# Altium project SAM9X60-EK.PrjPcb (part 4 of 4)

## Sheet 13 - On Board JLINK.SchDoc
size B; CompanyName: Microchip Technology Inc.; Organization: Microchip Technology; Address1: 2355 West Chandler Blvd.; Address2: Chandler, AZ  85224; Address4: USA; DocumentNumber: 13; SheetNumber: 13; SheetTotal: 13; SheetTitle: On Board JLINK
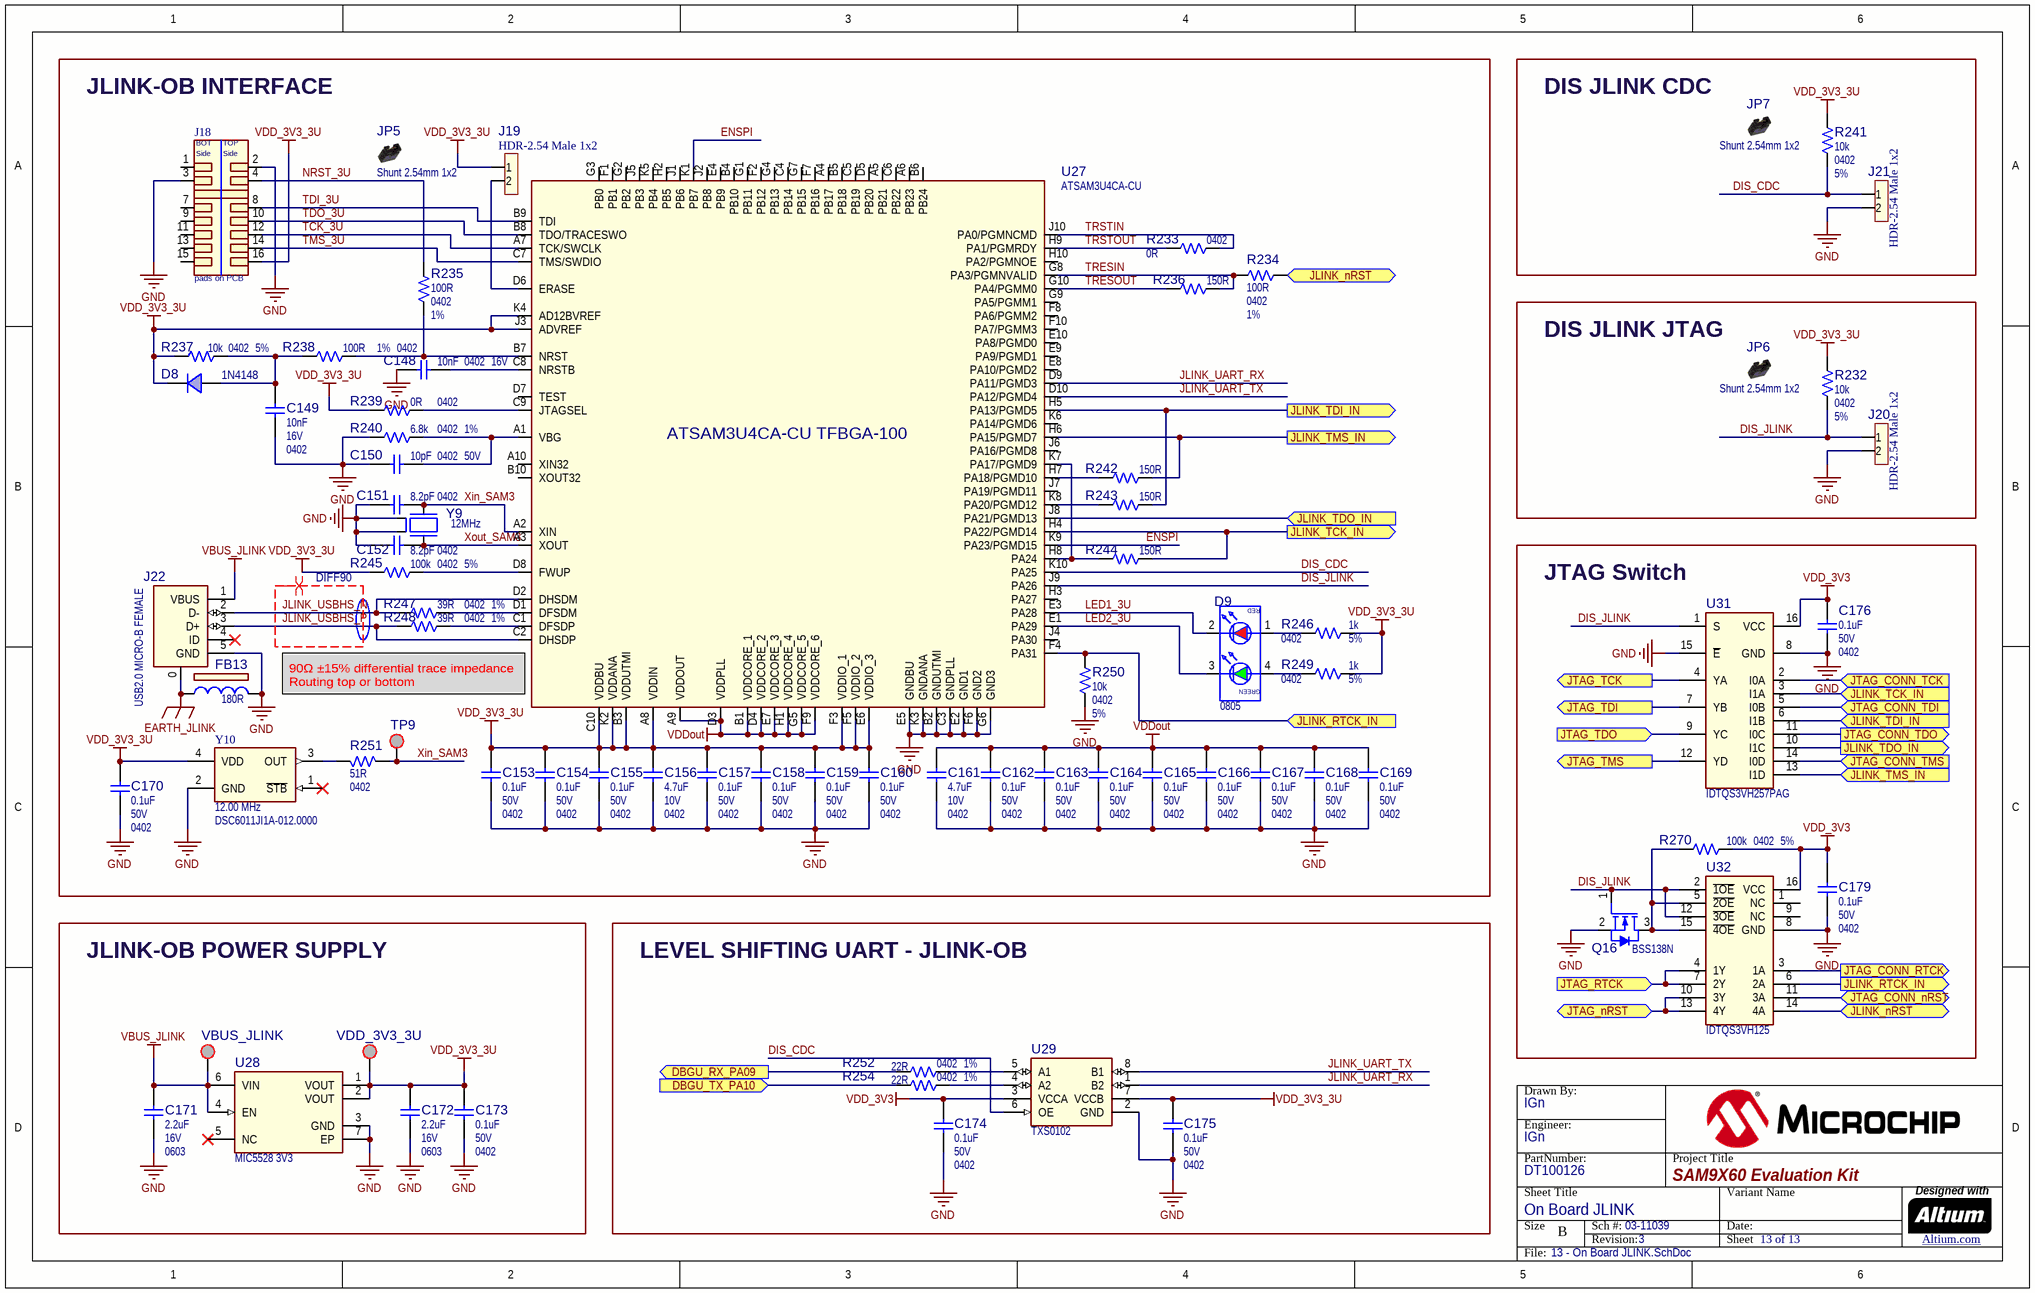
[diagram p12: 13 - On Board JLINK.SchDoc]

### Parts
(Parts that share a designator on the sheet are numbered #1, #2 ... from top to bottom, then left to right.)
?#13  (no value)  (graphical)
C148  value 10nF  Voltage: 16V  Package: 0402  [CAP_C_0402]  (hidden comment: Capacitor NP)
C149  value 10nF  Voltage: 16V  Package: 0402  [CAP_C_0402]  (hidden comment: Capacitor NP)
C150  value 10pF  Voltage: 50V  Package: 0402  [CAP_C_0402]  (hidden comment: Capacitor NP)
C151  value 8.2pF  Package: 0402  [CAP_C_0402]  (hidden comment: Capacitor NP)
C152  value 8.2pF  Package: 0402  [CAP_C_0402]  (hidden comment: Capacitor NP)
C153  value 0.1uF  Voltage: 50V  Package: 0402  [CAP_C_0402]  (hidden comment: Capacitor NP)
C154  value 0.1uF  Voltage: 50V  Package: 0402  [CAP_C_0402]  (hidden comment: Capacitor NP)
C155  value 0.1uF  Voltage: 50V  Package: 0402  [CAP_C_0402]  (hidden comment: Capacitor NP)
C156  value 4.7uF  Voltage: 10V  Package: 0402  [CAP_C_0402]  (hidden comment: Capacitor NP)
C157  value 0.1uF  Voltage: 50V  Package: 0402  [CAP_C_0402]  (hidden comment: Capacitor NP)
C158  value 0.1uF  Voltage: 50V  Package: 0402  [CAP_C_0402]  (hidden comment: Capacitor NP)
C159  value 0.1uF  Voltage: 50V  Package: 0402  [CAP_C_0402]  (hidden comment: Capacitor NP)
C160  value 0.1uF  Voltage: 50V  Package: 0402  [CAP_C_0402]  (hidden comment: Capacitor NP)
C161  value 4.7uF  Voltage: 10V  Package: 0402  [CAP_C_0402]  (hidden comment: Capacitor NP)
C162  value 0.1uF  Voltage: 50V  Package: 0402  [CAP_C_0402]  (hidden comment: Capacitor NP)
C163  value 0.1uF  Voltage: 50V  Package: 0402  [CAP_C_0402]  (hidden comment: Capacitor NP)
C164  value 0.1uF  Voltage: 50V  Package: 0402  [CAP_C_0402]  (hidden comment: Capacitor NP)
C165  value 0.1uF  Voltage: 50V  Package: 0402  [CAP_C_0402]  (hidden comment: Capacitor NP)
C166  value 0.1uF  Voltage: 50V  Package: 0402  [CAP_C_0402]  (hidden comment: Capacitor NP)
C167  value 0.1uF  Voltage: 50V  Package: 0402  [CAP_C_0402]  (hidden comment: Capacitor NP)
C168  value 0.1uF  Voltage: 50V  Package: 0402  [CAP_C_0402]  (hidden comment: Capacitor NP)
C169  value 0.1uF  Voltage: 50V  Package: 0402  [CAP_C_0402]  (hidden comment: Capacitor NP)
C170  value 0.1uF  Voltage: 50V  Package: 0402  [CAP_C_0402]  (hidden comment: Capacitor NP)
C171  value 2.2uF  Voltage: 16V  Package: 0603  [CAP_C_0603]  (hidden comment: Capacitor NP)
C172  value 2.2uF  Voltage: 16V  Package: 0603  [CAP_C_0603]  (hidden comment: Capacitor NP)
C173  value 0.1uF  Voltage: 50V  Package: 0402  [CAP_C_0402]  (hidden comment: Capacitor NP)
C174  value 0.1uF  Voltage: 50V  Package: 0402  [CAP_C_0402]  (hidden comment: Capacitor NP)
C175  value 0.1uF  Voltage: 50V  Package: 0402  [CAP_C_0402]  (hidden comment: Capacitor NP)
C176  value 0.1uF  Voltage: 50V  Package: 0402  [CAP_C_0402]  (hidden comment: Capacitor NP)
C179  value 0.1uF  Voltage: 50V  Package: 0402  [CAP_C_0402]  (hidden comment: Capacitor NP)
D8  value 1N4148  [SOD-323]  (hidden comment: Diode Single)
D9  Package: 0805  [LED_DUAL_SMD_2x1.25mm]  (hidden comment: LED DUAL 4 pin)
FB13  value 180R  [IND_C_0603]  (hidden comment: Ferrite Bead)
J18  pads on PCB  [CON_EDGE-CARD_PCB_RA_MEC1-108-02-F-D-RA1-SL]  (no BOM)
J19  value HDR-2.54 Male 1x2  [HDR_M_2.54_1x2]  (hidden comment: Header 1x2)
J20  value HDR-2.54 Male 1x2  [HDR_M_2.54_1x2]  (hidden comment: Header 1x2)
J21  value HDR-2.54 Male 1x2  [HDR_M_2.54_1x2]  (hidden comment: Header 1x2)
J22  value USB2.0 MICRO-B FEMALE  [CON_USB_Micro-AB_SMD_TH_RA_FCI_10118194-0001LF]  (hidden comment: CON USB2.0 Mini_Micro)
JP5  value Shunt 2.54mm 1x2  [Jumper_Mechanical]  (hidden comment: Jumper Mechanical)  (mechanical)
JP6  value Shunt 2.54mm 1x2  [Jumper_Mechanical]  (hidden comment: Jumper Mechanical)  (mechanical)
JP7  value Shunt 2.54mm 1x2  [Jumper_Mechanical]  (hidden comment: Jumper Mechanical)  (mechanical)
Q16  value BSS138N  [SOT-23-3]  (hidden comment: Transistor MOS-N GSD)
R232  value 10k  Package: 0402  Tolerance: 5%  [RES_C_0402]  (hidden comment: Resistor)
R233  value 0R  Package: 0402  [RES_C_0402]  (hidden comment: Resistor)
R234  value 100R  Package: 0402  Tolerance: 1%  [RES_C_0402]  (hidden comment: Resistor)
R235  value 100R  Package: 0402  Tolerance: 1%  [RES_C_0402]  (hidden comment: Resistor)
R236  value 150R  [RES_C_0402]  (hidden comment: Resistor)
R237  value 10k  Package: 0402  Tolerance: 5%  [RES_C_0402]  (hidden comment: Resistor)
R238  value 100R  Package: 0402  Tolerance: 1%  [RES_C_0402]  (hidden comment: Resistor)
R239  value 0R  Package: 0402  [RES_C_0402]  (hidden comment: Resistor)
R240  value 6.8k  Package: 0402  Tolerance: 1%  [RES_C_0402]  (hidden comment: Resistor)
R241  value 10k  Package: 0402  Tolerance: 5%  [RES_C_0402]  (hidden comment: Resistor)
R242  value 150R  [RES_C_0402]  (hidden comment: Resistor)
R243  value 150R  [RES_C_0402]  (hidden comment: Resistor)
R244  value 150R  [RES_C_0402]  (hidden comment: Resistor)
R245  value 100k  Package: 0402  Tolerance: 5%  [RES_C_0402]  (hidden comment: Resistor)
R246  value 1k  Package: 0402  Tolerance: 5%  [RES_C_0402]  (hidden comment: Resistor)
R247  value 39R  Package: 0402  Tolerance: 1%  [RES_C_0402]  (hidden comment: Resistor)
R248  value 39R  Package: 0402  Tolerance: 1%  [RES_C_0402]  (hidden comment: Resistor)
R249  value 1k  Package: 0402  Tolerance: 5%  [RES_C_0402]  (hidden comment: Resistor)
R250  value 10k  Package: 0402  Tolerance: 5%  [RES_C_0402]  (hidden comment: Resistor)
R251  value 51R  Package: 0402  [RES_C_0402]  (hidden comment: Resistor)
R252  value 22R  Package: 0402  Tolerance: 1%  [RES_C_0402]  (hidden comment: Resistor)
R254  value 22R  Package: 0402  Tolerance: 1%  [RES_C_0402]  (hidden comment: Resistor)
R270  value 100k  Package: 0402  Tolerance: 5%  [RES_C_0402]  (hidden comment: Resistor)
TP9  SMD Test Point  [TP_1x1_SMD]  (value not drawn)  (no BOM)
U27  ATSAM3U4CA-CU TFBGA-100  value ATSAM3U4CA-CU  [TFBGA-100_P0.8_9x9x1.1]
U28  value MIC5528 3V3  [DFN-6_1.2x1.2]  (hidden comment: MIC5528MT DFN-6)
U29  TXS0102  [US-8]
U31  value IDTQS3VH257PAG  [TSSOP-16]  (hidden comment: IDTQS3VH257 TSSOP-16)
U32  value IDTQS3VH125  [QSOP-16]  (hidden comment: IDTQS3VH125 SSOP-16)
VBUS_JLINK  SMD Test Point  [TP_1x1_SMD]  (value not drawn)  (no BOM)
VDD_3V3_3U  SMD Test Point  [TP_1x1_SMD]  (value not drawn)  (no BOM)
Y9  value 12MHz  [CRYSTAL_L7.5W5.2H1.4]  (hidden comment: Crystal 4 Pins)
Y10  value 12.00 MHz  Manufacturer Part Number 1: DSC6011JI1A-012.0000  [OSCILLATOR_DSC60000L2.5W2.0H0.89]  (hidden comment: OSCILLATOR DSC60XX)

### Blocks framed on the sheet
JLINK-OB INTERFACE: C148-C170 D8 D9 FB13 J18 J19 J22 JP5 R233-R240 R242-R251 TP9 U27 Y9 Y10
DIS JLINK CDC: J21 JP7 R241
DIS JLINK JTAG: J20 JP6 R232
JTAG Switch: C176 C179 Q16 R270 U31 U32
JLINK-OB POWER SUPPLY: C171-C173 U28 VBUS_JLINK VDD_3V3_3U
LEVEL SHIFTING UART - JLINK-OB: C174 C175 R252 R254 U29

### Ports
DBGU_RX_PA09 (out), DBGU_TX_PA10 (in), JLINK_nRST (bidir), JLINK_RTCK_IN (in), JLINK_RTCK_IN (out), JLINK_TCK_IN (in), JLINK_TCK_IN (out), JLINK_TDI_IN (in), JLINK_TDI_IN (out), JLINK_TDO_IN (in), JLINK_TDO_IN (out), JLINK_TMS_IN (in), JLINK_TMS_IN (out), JTAG_CONN_nRST (bidir), JTAG_CONN_RTCK (out), JTAG_CONN_TCK (in), JTAG_CONN_TDI (in), JTAG_CONN_TDO (out), JTAG_CONN_TMS (in), JTAG_nRST (bidir), JTAG_RTCK (in), JTAG_TCK (out), JTAG_TDI (out), JTAG_TDO (in), JTAG_TMS (out)

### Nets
EARTH_JLINK: FB13.1 J22.0(SHLD)
GND: C148.1 C149.1 C150.2 C151.2 C152.2 C153.2 C154.1 C155.2 C156.1 C157.1 C158.1 C159.1 C160.1 C161.1 C162.1 C163.2 C164.2 C165.2 C166.2 C167.2 C168.2 C169.1 C170.1 C171.2 C172.1 C173.1 C174.1 C175.1 C176.2 C179.2 FB13.2 J18.2 J18.3 J20.2 J21.2 J22.5(GND) Q16.2(S) R240.1 R250.2 U27.B2(GNDUTMI) U27.C3(GNDPLL) U27.E2(GND1) U27.E5(GNDBU) U27.F6(GND2) U27.G6(GND3) U27.K3(GNDANA) U28.3(GND) U28.7(EP) U29.2(GND) U31.8(GND) U31.15(~{E}) U32.8(GND) Y9.2(GND) Y9.4(GND) Y10.2(GND)
VBUS_JLINK: C171.1 J22.1(VBUS) U28.4(EN) U28.6(VIN) VBUS_JLINK.1
VDD_3V3: C174.2 C176.1 C179.1 R270.1 U29.3(VCCA) U31.16(VCC) U32.16(VCC)
VDD_3V3_3U: C153.1 C154.2 C155.1 C156.2 C157.2 C158.2 C159.2 C160.2 C170.2 C172.2 C173.2 C175.2 D8.2(K) J18.16 J19.1 R232.1 R237.1 R239.1 R241.1 R245.1 R246.1 R249.1 U27.A8(VDDIN) U27.B3(VDDUTMI) U27.C10(VDDBU) U27.E6(VDDIO_3) U27.F3(VDDIO_1) U27.F5(VDDIO_2) U27.J3(ADVREF) U27.K2(VDDANA) U27.K4(AD12BVREF) U28.1(VOUT) U28.2(VOUT) U29.7(VCCB) VDD_3V3_3U.1 Y10.4(VDD)
VDDout: C161.2 C162.2 C163.1 C164.1 C165.1 C166.1 C167.1 C168.1 C169.2 U27.A9(VDDOUT) U27.B1(VDDCORE_1) U27.D3(VDDPLL) U27.D4(VDDCORE_2) U27.E7(VDDCORE_3) U27.F9(VDDCORE_6) U27.G5(VDDCORE_5) U27.H1(VDDCORE_4)
DBGU_RX_PA09: R252.1 ; port DBGU_RX_PA09
DBGU_TX_PA10: R254.1 ; port DBGU_TX_PA10
DIS_CDC: J21.1 R241.2 U27.K10(PA25) U29.6(OE)
DIS_JLINK: J20.1 Q16.1(G) R232.2 U27.J9(PA26) U31.1(S) U32.2(~{1OE}) U32.12(~{3OE})
ENSPI: U27.K1(PB7) U27.K9(PA23/PGMD15)
JLINK_nRST: R234.2 U32.14(4A) ; port JLINK_nRST
JLINK_RTCK_IN: R250.1 U27.F4(PA31) U32.6(2A) ; port JLINK_RTCK_IN
JLINK_TCK_IN: R244.2 U27.H4(PA22/PGMD14) U31.3(I1A) ; port JLINK_TCK_IN
JLINK_TDI_IN: R243.2 U27.H5(PA13/PGMD5) U31.6(I1B) ; port JLINK_TDI_IN
JLINK_TDO_IN: U27.J8(PA21/PGMD13) U31.10(I1C) ; port JLINK_TDO_IN
JLINK_TMS_IN: R242.2 U27.H6(PA15/PGMD7) U31.13(I1D) ; port JLINK_TMS_IN
JLINK_UART_RX: U27.D9(PA11/PGMD3) U29.1(B2)
JLINK_UART_TX: U27.D10(PA12/PGMD4) U29.8(B1)
JLINK_USBHS_N: J22.2(D-) R247.1 U27.D2(DHSDM)
JLINK_USBHS_P: J22.3(D+) R248.1 U27.C2(DHSDP)
JTAG_CONN_nRST: U32.11(3A) ; port JTAG_CONN_nRST
JTAG_CONN_RTCK: U32.3(1A) ; port JTAG_CONN_RTCK
JTAG_CONN_TCK: U31.2(I0A) ; port JTAG_CONN_TCK
JTAG_CONN_TDI: U31.5(I0B) ; port JTAG_CONN_TDI
JTAG_CONN_TDO: U31.11(I0C) ; port JTAG_CONN_TDO
JTAG_CONN_TMS: U31.14(I0D) ; port JTAG_CONN_TMS
JTAG_nRST: U32.10(3Y) U32.13(4Y) ; port JTAG_nRST
JTAG_RTCK: U32.4(1Y) U32.7(2Y) ; port JTAG_RTCK
JTAG_TCK: U31.4(YA) ; port JTAG_TCK
JTAG_TDI: U31.7(YB) ; port JTAG_TDI
JTAG_TDO: U31.9(YC) ; port JTAG_TDO
JTAG_TMS: U31.12(YD) ; port JTAG_TMS
LED1_3U: D9.2(K1) U27.E3(PA28)
LED2_3U: D9.3(K2) U27.E1(PA29)
NRST_3U: J18.4 R235.2
TCK_3U: J18.12 U27.A7(TCK/SWCLK)
TDI_3U: J18.8 U27.B9(TDI)
TDO_3U: J18.10 U27.B8(TDO/TRACESWO)
TMS_3U: J18.14 U27.C7(TMS/SWDIO)
TRESIN: R234.1 R236.2 U27.G8(PA3/PGMNVALID)
TRESOUT: R236.1 U27.G10(PA4/PGMM0)
TRSTIN: R233.2 U27.J10(PA0/PGMNCMD)
TRSTOUT: R233.1 U27.H9(PA1/PGMRDY)
Xin_SAM3: C151.1 R251.2 TP9.1 U27.A2(XIN) Y9.1(Osc1)
Xout_SAM3: C152.1 U27.A3(XOUT) Y9.3(Osc2)
NetC148_2: C148.2 U27.C8(NRSTB)
NetC149_2: C149.2 D8.1(A) R237.2 R238.1
NetC150_1: C150.1 R240.2 U27.A1(VBG)
NetD9_1: D9.1(A1) R246.2
NetD9_4: D9.4(A2) R249.2
NetJ19_2: J19.2 U27.D6(ERASE)
NetQ16_3: Q16.3(D) R270.2 U32.5(~{2OE}) U32.15(~{4OE})
NetR235_1: R235.1 R238.2 U27.B7(NRST)
NetR239_2: R239.2 U27.C9(JTAGSEL)
NetR242_1: R242.1 U27.H7(PA18/PGMD10)
NetR243_1: R243.1 U27.K8(PA20/PGMD12)
NetR244_1: R244.1 U27.H8(PA24) U27.K7(PA17/PGMD9)
NetR245_2: R245.2 U27.D8(FWUP)
NetR247_2: R247.2 U27.D1(DFSDM)
NetR248_2: R248.2 U27.C1(DFSDP)
NetR251_1: R251.1 Y10.3(OUT)
NetR252_2: R252.2 U29.5(A1)
NetR254_2: R254.2 U29.4(A2)

Not connected (* = marked no-connect by the designer): J18 1 7 9 11 13 15; J22 4(ID)*; U27 A4(PB17) A5(PB21) A6(PB23) A10(XIN32) B4(PB10) B5(PB18) B6(PB24) B10(XOUT32) C4(PB14) C5(PB19) C6(PB22) D5(PB20) D7(TEST) E4(PB9) E8(PA10/PGMD2) E9(PA9/PGMD1) E10(PA8/PGMD0) F1(PB1) F2(PB12) F7(PB16) F8(PA6/PGMM2) F10(PA7/PGMM3) G1(PB11) G2(PB2) G3(PB0) G4(PB13) G7(PB15) G9(PA5/PGMM1) H2(PB5) H3(PA27) H10(PA2/PGMNOE) J1(PB6) J2(PB8) J4(PA30) J5(PB3) J6(PA16/PGMD8) J7(PA19/PGMD11) K5(PB4) K6(PA14/PGMD6); U28 5(NC)*; U32 1(NC) 9(NC); Y10 1(~{STB})*

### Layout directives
differential pair; differential pair class DIFF90; net class DIFF90; rule Matched Net Lengths [Tolerance = 10mil]: JLINK_USBHS_N, JLINK_USBHS_P

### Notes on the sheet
- (near U27) 90Ω ±15% differential trace impedance
  Routing top or bottom

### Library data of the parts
?#13 = Title Block B
C148 C149 = CAP0278: Capacitor; Manufacturer 1: KEMET; Manufacturer Part Number 1: C0402C103K4RACTU; Description_: CAP CER 10000pF 16V 10% X7R SMD 0402; Dev Tools Status: Production; Tolerance: 10%; Temperature Coeffcient: X7R; Type: Ceramic; Populated: YES
C150 = CAP0613: Capacitor; Manufacturer 1: Murata; Manufacturer Part Number 1: GRM1555C1H100JZ01D; Description_: CAP CER 10pF 50V 5% NP0 SMD 0402; Dev Tools Status: Production; Tolerance: 5%; Temperature Coeffcient: NP0; Type: Ceramic; Populated: Yes
C151 C152 = CAP1379: Capacitor; Manufacturer 1: Johanson Technology Inc; Manufacturer Part Number 1: 500R07S8R2CV4T; Voltage: 50V; Description_: CAP HiQ 8.2pF 50V 0.25pF NP0 3.04GHz SMD 0402; Dev Tools Status: Production; Tolerance: 0.25pF; Temperature Coeffcient: NP0; ESR: 0.04R; Type: HiQ; Owner: Gabor Bihari; Populated: DNP
C153-C155 C157-C160 C162-C170 C173-C176 C179 = CAP1463: Capacitor; Manufacturer 1: TDK Corporation; Manufacturer Part Number 1: C1005X7R1H104K050BB; Description_: CAP CER 0.1uF 50V 10% X7R SMD 0402; Dev Tools Status: Production; Tolerance: 10%; Temperature Coeffcient: X7R; Type: Ceramic; Owner: Jamus Griego; Populated: YES
C156 C161 = CAP1684: Capacitor; Manufacturer 1: TDK Corporation; Manufacturer Part Number 1: C1005X5R1A475K050BC; Description_: CAP CER 4.7uF 10V 10% X5R SMD 0402; Dev Tools Status: Design; Tolerance: 10%; Temperature Coeffcient: X5R; Type: Ceramic; Owner: Jesus Aviles; Populated: YES
C171 C172 = CAP0597: Capacitor; Manufacturer 1: TDK; Manufacturer Part Number 1: C1608X5R1C225K; Description_: CAP CER 2.2uF 16V 10% X5R SMD 0603; Dev Tools Status: Production; Tolerance: 10%; Temperature Coeffcient: X5R; Type: Ceramic; Populated: Yes
D8 = DIODE0096: Manufacturer 1: Diodes Incorporated; Manufacturer Part Number 1: 1N4148WS-7-F; Description_: DIO RECT 1N4148WS 1.25V 150mA 75V SOD-323; Dev Tools Status: Production; Type: Rectifier Single; Forward Current: 150mA; Power: 200mW; Reverse Current: 50uA; Reverse Voltage: 75V; Populated: YES
D9 = DIODE1110: LED; Manufacturer 1: Kingbright Corp; Manufacturer Part Number 1: APHBM2012SURKCGKC; Value: RED, GREEN; Description_: DIO LED BI RED, GREEN 1.95V, 2.1V 30mA 0805; Dev Tools Status: Production; Type: LED Bicolor; Forward Current: 30mA; Power: 75mW; Reverse Current: 10uA; Owner: Bogdan P (M91398); Populated: Yes
FB13 = IND1453: FERRITE 180R 1.5A SMD 0603; Manufacturer 1: Murata Electronics North America; Manufacturer Part Number 1: BLM18PG181SN1D; Dev Tools Status: Design; Owner: Dragos Danaila; DCR: 0.09R; Test Frequency: 100MHz; Populated: YES
J18 = CON1674: CON_PCB_MEC1-108-02-F-D-RA1-SL; Manufacturer 1: Samtec Inc.; Description_: CON EDGE MEC1 1mm 14P Male PCB VERT; Dev Tools Status: Design; Owner: Dragos Danaila; Current: 1.6A; Populated: NO
J19 = CON1312: Manufacturer 1: Sullins Connector Solutions; Manufacturer Part Number 1: PREC002SAAN-RC; Description_: CON HDR-2.54 Male 1x2 Tin 5.84MH TH VERT; Dev Tools Status: Production; Owner: Randolph Sobrepena; Populated: DNP
J20 J21 = CON1312: Manufacturer 1: Sullins Connector Solutions; Manufacturer Part Number 1: PREC002SAAN-RC; Description_: CON HDR-2.54 Male 1x2 Tin 5.84MH TH VERT; Dev Tools Status: Production; Owner: Randolph Sobrepena; Populated: YES
J22 = CON1383: Connector USB Mini; Manufacturer 1: FCI; Manufacturer Part Number 1: 10118194-0001LF; Description_: CON USB2.0 MICRO-B FEMALE TH/SMD R/A; Dev Tools Status: Production; Owner: Jamus Griego; Populated: YES
JP5 = HW1006: Manufacturer 1: 3M; Manufacturer Part Number 1: 969102-0000-DA; MCHP-ID: HW1006; Description_: MECH HW JUMPER 2.54mm 1x2; Dev Tools Status: Production; Owner: Mike Ragsdale; Populated: DNP
JP6 JP7 = HW1006: Manufacturer 1: 3M; Manufacturer Part Number 1: 969102-0000-DA; MCHP-ID: HW1006; Description_: MECH HW JUMPER 2.54mm 1x2; Dev Tools Status: Production; Owner: Mike Ragsdale; Populated: MECH
Q16 = TRA1223: Transistor MOS; Manufacturer 1: Infineon Technologies; Manufacturer Part Number 1: BSS138NH6327XTSA2; Description_: TRANS FET N-CH BSS138N 60V 230mA SOT23-3; Dev Tools Status: Production; Type: FET; Current: 230mA; Drain to Source Voltage: 60V; Gate to Source Voltage: 20V; Power: 0.36W; Owner: Dragos Danaila; Populated: YES
R232 R237 R241 R250 = RSMT0439: Manufacturer 1: Vishay; Manufacturer Part Number 1: CRCW040210K0JNED; Description_: RES TKF 10k 5% 1/16W SMD 0402; Dev Tools Status: Production; Voltage: 50V; Temperature Coeffcient: 100ppm/C; Power: 1/16W; Populated: Yes
R233 = RSMT1040: Manufacturer 1: Yageo; Manufacturer Part Number 1: RC0402JR-070RL; Description_: RES TKF 0R 1/16W SMD 0402; Dev Tools Status: Production; Power: 1/16W; Owner: Sompoch Loboonlert; Populated: Yes
R234 R235 R238 = RES1587: Manufacturer 1: Yageo; Manufacturer Part Number 1: RC0402FR-07100RL; Description_: RES TKF 100R 1% 1/16W SMD 0402; Dev Tools Status: Design; Voltage: 50V; Temperature Coeffcient: 100ppm/C; Power: 1/16W; Owner: Sorin Stanoaia; Populated: YES
R236 R242-R244 = RSMT1167: Manufacturer 1: Vishay Dale; Manufacturer Part Number 1: CRCW0402150RFKED; Description_: RES TKF 150R 1% 1/16W MF 0402; Dev Tools Status: Production; Owner: Jamus Griego; Populated: YES
R239 = RSMT1040: Manufacturer 1: Yageo; Manufacturer Part Number 1: RC0402JR-070RL; Description_: RES TKF 0R 1/16W SMD 0402; Dev Tools Status: Production; Power: 1/16W; Owner: Sompoch Loboonlert; Populated: DNP
R240 = RSMT1211: Manufacturer 1: Vishay Dale; Manufacturer Part Number 1: CRCW04026K80FKED; Description_: RES TKF 6.8k 1% 1/16W SMD 0402; Dev Tools Status: Design; Voltage: 50V; Temperature Coeffcient: 100ppm/C; Power: 1/16W; Owner: Dragos Danaila; Populated: YES
R245 R270 = RES2196: Manufacturer 1: Yageo; Manufacturer Part Number 1: RC0402JR-07100KL; Description_: RES TKF 100k 5% 1/16W SMD 0402; Dev Tools Status: Design; Temperature Coeffcient: 100ppm/C; Power: 1/16W; Owner: Ilie Galan; Populated: YES
R246 R249 = RSMT0316: Manufacturer 1: Panasonic; Manufacturer Part Number 1: ERJ-2GEJ102X; Description_: RES TKF 1k 5% 1/16W SMD 0402; Dev Tools Status: Production; Voltage: 50V; Temperature Coeffcient: 200ppm/C; Power: 1/16W; Owner: Tad Ahlvers; Populated: YES
R247 R248 = RES1800: Manufacturer 1: Yageo; Manufacturer Part Number 1: RC0402FR-0739RL; Description_: RES TKF 39R 1% 1/16W SMD 0402; Dev Tools Status: Design; Circuit Type: Single; Power: 1/16W; Owner: Sompoch Loboonlert; Populated: YES
R251 = RSMT1243: Manufacturer 1: Yageo; Manufacturer Part Number 1: RC0402FR-0751RL; Tolerance: 1%; Description_: RES TKF 51R 1% 1/16W SMD 0402; Dev Tools Status: Design; Voltage: 100V; Temperature Coeffcient: 100ppm/C; Current: 1A; Power: 1/16W; Owner: Ciprian Abramov; Populated: YES
R252 R254 = RES1474: Manufacturer 1: Panasonic Electronic Components; Manufacturer Part Number 1: ERJ-2RKF22R0X; Description_: RES TKF 22R 1% 1/20W SMD 0402; Dev Tools Status: Production; Temperature Coeffcient: 100ppm/C; Circuit Type: Isolated; Power: 1/10W; Owner: Mike Ragsdale; Populated: YES
TP9 VBUS_JLINK VDD_3V3_3U = TEST-POINT: Test Point pad 1.00mm
U27 = MIC7470: Manufacturer 1: Microchip Technology; Description_: MCHP MCU 32-BIT 96MHz 256kB 56kB ATSAM3U4CA-CU 100BGA; MAPS Description: TFBGA,GREEN,IND TEMP,MRL A; Dev Tools Status: Design; Owner: Dragos Danaila; MPC: 58Z247A2BC02; LeadContent: Pb-FREE; TempRange: -40C to +85C; Stage: REL; PackageWidth: 9x9x1.2mm; PackingMedia: TRAY; ForceMinOrderQtyMult: True; MinOrderQty: 260; LeadCount: 100; Program Memory KBytes: 256; Program Memory KWords: 64; Ram: 51200; EEPROM: 0; IOPins: 57; MaxSpeed: 96; OscillatorMHz: 4,8,12Mhz,32Khz; ADC Channels: 8; ADCBit: 12; USART: 4; I2C: 1; Input Capture: 6; CapTouchCH: 28; DigitalTimerQty_16bit: 3; Populated: YES
U28 = MIC6905: Manufacturer 1: Microchip Technology; Manufacturer Part Number 1: MIC5528-3.3YMT-TR; Description_: MCHP ANALOG LDO 3.3V MIC5528-3.3YMT-TR 6-TDFN; MAPS Description: Single, 500mA LDO w/ Auto Discharge & Internal Enable Pulldown; Dev Tools Status: Production; Owner: Tim Moffat; MPC: TKFC1YHHAA02; LeadContent: Pb-FREE; PackingMedia: T/R; Stage: REL; LeadCount: 6; PackageWidth: 1.2x1.2x0.6mm; ForceMinOrderQtyMult: True; MinOrderQty: 1; TempRange: -40C to +125C; tblDeviceFamilyID: 7519; Populated: YES
U29 = IC1128: Level Shifter; Manufacturer 1: Texas Instruments; Manufacturer Part Number 1: TXS0102DCUR; MCHP-ID: IC1128; Description_: IC TRANSCEIVER TXS0102 US-8; Dev Tools Status: Production; Owner: Bogdan P (M91398); Populated: Yes
U31 = IC1517: Manufacturer 1: IDT, Integrated Device Technology Inc; Manufacturer Part Number 1: QS3VH257PAG; MCHP-ID: IC1517; Description_: IC SWITCHER  MUX/DEMUX IDTQS3VH257 QUAD 2:1 TSSOP-16; Dev Tools Status: Design; Owner: Ilie Galan; Populated: YES
U32 = IC1516: Manufacturer 1: IDT, Integrated Device Technology Inc; Manufacturer Part Number 1: QS3VH125QG; MCHP-ID: IC1516; Description_: IC SWITCHER IDTQS3VH125 Bus Switch 1 x 4:1 QSOP-16; Dev Tools Status: Design; Owner: Ilie Galan; Populated: YES
Y9 = OSC1155: Crystal; Manufacturer 1: IQD Frequency Products; Manufacturer Part Number 1: LFXTAL026384Reel; Description_: CRYSTAL 12MHz 16pF SMD L7.5W5.0H1.4; Dev Tools Status: Design; Owner: Dragos Danaila; Tolerance: 30ppm; Load Capacitance: 16pF; Populated: DNP
Y10 = MIC7210: Manufacturer 1: Microchip Technology Inc; Description_: MCHP CLOCK OSCILLATOR SINGLE 12.000MHZ DSC6011JI1A-012.0000 VLGA; Dev Tools Status: Production; Owner: Tim Moffat; Populated: YES

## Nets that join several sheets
DDR_VREF: 03 - Processor SAM9X60 (5 pins), 06 - On Board Memories (C64.1 U10.J2)
GND: 02 - Power supply (42 pins), 03 - Processor SAM9X60 (60 pins), 05 - Processor IO Expansions (18 pins), 06 - On Board Memories (49 pins), 07 - USB ports (23 pins), 08 - Ethernet MAC (18 pins), 09 - Wi-Fi BT module (23 pins), 10 - SDMMC, CAN & CLASSD (28 pins), 11 - Expansion connectors (27 pins), 12 - User Interaction (38 pins), 13 - On Board JLINK (55 pins)
USBA_VBUS_5V: 02 - Power supply (C7.1 FB1.1), 07 - USB ports (C106.2 J7.1 R148.1 VBUS_USBA.1)
VDD_3V3: 02 - Power supply (6 pins), 03 - Processor SAM9X60 (C29.2 Y3.4), 05 - Processor IO Expansions (23 pins), 06 - On Board Memories (23 pins), 07 - USB ports (R152.2 R154.2), 08 - Ethernet MAC (11 pins), 09 - Wi-Fi BT module (17 pins), 10 - SDMMC, CAN & CLASSD (14 pins), 11 - Expansion connectors (5 pins), 12 - User Interaction (20 pins), 13 - On Board JLINK (7 pins)
VDD_3V3_MPU: 02 - Power supply (R9.2 VDD_3V3.1), 03 - Processor SAM9X60 (16 pins)
VDD_MAIN_5V: 02 - Power supply (8 pins), 07 - USB ports (6 pins), 09 - Wi-Fi BT module (C126.1 U22.1 U22.2), 10 - SDMMC, CAN & CLASSD (5 pins), 11 - Expansion connectors (J14.10 J16.2 J16.4 R214.2)
VDDBU: 02 - Power supply (J2.1), 03 - Processor SAM9X60 (C50.1 R22.1 U5.P7), 12 - User Interaction (R194.2)
VDDCORE: 02 - Power supply (R8.2 VDDCORE.1), 03 - Processor SAM9X60 (7 pins)
VDDIOM: 02 - Power supply (R7.2 VDDIOM.1), 03 - Processor SAM9X60 (10 pins), 06 - On Board Memories (32 pins)
CAN0_RX: 05 - Processor IO Expansions (U15.5), 10 - SDMMC, CAN & CLASSD (C97.2 U12.4)
CAN0_TX: 05 - Processor IO Expansions (U15.6), 10 - SDMMC, CAN & CLASSD (U12.1)
CAN1_RX: 05 - Processor IO Expansions (U14.5), 10 - SDMMC, CAN & CLASSD (C101.2 U13.4)
CAN1_TX: 05 - Processor IO Expansions (U14.6), 10 - SDMMC, CAN & CLASSD (U13.1)
CAN/DBGU_RX_PA09: 04 - Processor IOs (U5.G8), 05 - Processor IO Expansions (R143.2 R147.2)
CAN/DBGU_TX_PA10: 04 - Processor IOs (U5.L2), 05 - Processor IO Expansions (R141.2 R145.2)
CAN/FLEXCOM_RX_PA06: 04 - Processor IOs (U5.M2), 05 - Processor IO Expansions (R142.2 R146.2)
CAN/FLEXCOM_TX_PA05: 04 - Processor IOs (U5.L4), 05 - Processor IO Expansions (R140.2 R144.2)
CAN_STBY_PD21: 04 - Processor IOs (U5.M15), 10 - SDMMC, CAN & CLASSD (U12.8 U13.8)
CLASSD_L0_PA24: 04 - Processor IOs (U5.F8), 10 - SDMMC, CAN & CLASSD (R177.1)
CLASSD_L1_PA25: 04 - Processor IOs (U5.H1), 10 - SDMMC, CAN & CLASSD (R178.1)
CLASSD_L2_PA26: 04 - Processor IOs (U5.F7), 10 - SDMMC, CAN & CLASSD (R181.1)
CLASSD_L3_PA27: 04 - Processor IOs (U5.H2), 10 - SDMMC, CAN & CLASSD (R182.1)
DBGU_RX_PA09: 05 - Processor IO Expansions (U17.5), 12 - User Interaction (R268.1), 13 - On Board JLINK (R252.1)
DBGU_TX_PA10: 05 - Processor IO Expansions (U17.6), 12 - User Interaction (R266.1), 13 - On Board JLINK (R254.1)
DDR_A2: 03 - Processor SAM9X60 (U5.A13), 06 - On Board Memories (U10.M8)
DDR_A3: 03 - Processor SAM9X60 (U5.D15), 06 - On Board Memories (U10.M3)
DDR_A4: 03 - Processor SAM9X60 (U5.B12), 06 - On Board Memories (U10.M7)
DDR_A5: 03 - Processor SAM9X60 (U5.E11), 06 - On Board Memories (U10.N2)
DDR_A6: 03 - Processor SAM9X60 (U5.A12), 06 - On Board Memories (U10.N8)
DDR_A7: 03 - Processor SAM9X60 (U5.B16), 06 - On Board Memories (U10.N3)
DDR_A8: 03 - Processor SAM9X60 (U5.F16), 06 - On Board Memories (U10.N7)
DDR_A9: 03 - Processor SAM9X60 (U5.D14), 06 - On Board Memories (U10.P2)
DDR_A10: 03 - Processor SAM9X60 (U5.C11), 06 - On Board Memories (U10.P8)
DDR_A11: 03 - Processor SAM9X60 (U5.E13), 06 - On Board Memories (U10.P3)
DDR_A13: 03 - Processor SAM9X60 (U5.B11), 06 - On Board Memories (U10.P7)
DDR_A14: 03 - Processor SAM9X60 (U5.C15), 06 - On Board Memories (U10.R2)
DDR_A15: 03 - Processor SAM9X60 (U5.G15), 06 - On Board Memories (U10.R8)
DDR_A16: 03 - Processor SAM9X60 (U5.E14), 06 - On Board Memories (U10.L2)
DDR_A17: 03 - Processor SAM9X60 (U5.F14), 06 - On Board Memories (U10.L3)
DDR_A18: 03 - Processor SAM9X60 (U5.C16), 06 - On Board Memories (U10.L1)
DDR_CAS: 03 - Processor SAM9X60 (U5.C12), 06 - On Board Memories (U10.L7)
DDR_CKE: 03 - Processor SAM9X60 (U5.F13), 06 - On Board Memories (U10.K2)
DDR_CLK_N: 03 - Processor SAM9X60 (U5.B14), 06 - On Board Memories (U10.K8)
DDR_CLK_P: 03 - Processor SAM9X60 (U5.A15), 06 - On Board Memories (U10.J8)
DDR_CS: 03 - Processor SAM9X60 (U5.E16), 06 - On Board Memories (U10.L8)
DDR_D0: 03 - Processor SAM9X60 (U5.J13), 06 - On Board Memories (U10.G8)
DDR_D1: 03 - Processor SAM9X60 (U5.H11), 06 - On Board Memories (U10.G2)
DDR_D2: 03 - Processor SAM9X60 (U5.J11), 06 - On Board Memories (U10.H7)
DDR_D3: 03 - Processor SAM9X60 (U5.H16), 06 - On Board Memories (U10.H3)
DDR_D4: 03 - Processor SAM9X60 (U5.H15), 06 - On Board Memories (U10.H1)
DDR_D5: 03 - Processor SAM9X60 (U5.J14), 06 - On Board Memories (U10.H9)
DDR_D6: 03 - Processor SAM9X60 (U5.H10), 06 - On Board Memories (U10.F1)
DDR_D7: 03 - Processor SAM9X60 (U5.J16), 06 - On Board Memories (U10.F9)
DDR_D8: 03 - Processor SAM9X60 (U5.A9), 06 - On Board Memories (U10.C8)
DDR_D9: 03 - Processor SAM9X60 (U5.F10), 06 - On Board Memories (U10.C2)
DDR_D10: 03 - Processor SAM9X60 (U5.B9), 06 - On Board Memories (U10.D7)
DDR_D11: 03 - Processor SAM9X60 (U5.C9), 06 - On Board Memories (U10.D3)
DDR_D12: 03 - Processor SAM9X60 (U5.G9), 06 - On Board Memories (U10.D1)
DDR_D13: 03 - Processor SAM9X60 (U5.F9), 06 - On Board Memories (U10.D9)
DDR_D14: 03 - Processor SAM9X60 (U5.D11), 06 - On Board Memories (U10.B1)
DDR_D15: 03 - Processor SAM9X60 (U5.D8), 06 - On Board Memories (U10.B9)
DDR_DQM0: 03 - Processor SAM9X60 (U5.G11), 06 - On Board Memories (U10.F3)
DDR_DQM1: 03 - Processor SAM9X60 (U5.C8), 06 - On Board Memories (U10.B3)
DDR_DQS0_N: 03 - Processor SAM9X60 (U5.H13), 06 - On Board Memories (U10.E8)
DDR_DQS0_P: 03 - Processor SAM9X60 (U5.H12), 06 - On Board Memories (U10.F7)
DDR_DQS1_N: 03 - Processor SAM9X60 (U5.E9), 06 - On Board Memories (U10.A8)
DDR_DQS1_P: 03 - Processor SAM9X60 (U5.D9), 06 - On Board Memories (U10.B7)
DDR_RAS: 03 - Processor SAM9X60 (U5.E15), 06 - On Board Memories (U10.K7)
DDR_SDA10: 03 - Processor SAM9X60 (U5.D12), 06 - On Board Memories (U10.M2)
DDR_WE: 03 - Processor SAM9X60 (U5.D16), 06 - On Board Memories (U10.K3)
EEPROM_TWCK: 05 - Processor IO Expansions (R76.2), 06 - On Board Memories (U7.1)
EEPROM_TWD: 05 - Processor IO Expansions (R67.2), 06 - On Board Memories (U7.3)
ETH0_IRQ_PB08: 04 - Processor IOs (U5.E6), 08 - Ethernet MAC (R122.2 U11.18)
ETH0_MDC_PB06: 04 - Processor IOs (U5.D2), 08 - Ethernet MAC (U11.11)
ETH0_MDIO_PB05: 04 - Processor IOs (U5.E1), 08 - Ethernet MAC (R123.2 U11.10)
ETH0_PCK1_PC31: 04 - Processor IOs (R88.1), 08 - Ethernet MAC (R133.2)
ETH0_RX0_PB00: 04 - Processor IOs (U5.F4), 08 - Ethernet MAC (U11.13)
ETH0_RX1_PB01: 04 - Processor IOs (U5.C1), 08 - Ethernet MAC (U11.12)
ETH0_RXDV_PB03: 04 - Processor IOs (U5.D1), 08 - Ethernet MAC (R127.1 U11.15)
ETH0_RXER_PB02: 04 - Processor IOs (U5.D3), 08 - Ethernet MAC (U11.17)
ETH0_TX0_PB09: 04 - Processor IOs (U5.A2), 08 - Ethernet MAC (U11.20)
ETH0_TX1_PB10: 04 - Processor IOs (U5.A3), 08 - Ethernet MAC (U11.21)
ETH0_TXCK_PB04: 04 - Processor IOs (U5.E3), 08 - Ethernet MAC (U11.16)
ETH0_TXEN_PB07: 04 - Processor IOs (U5.A5), 08 - Ethernet MAC (U11.19)
EXT40_CLK1_PC31: 04 - Processor IOs (R86.1), 11 - Expansion connectors (J16.29)
EXT40_CLK2_PB13: 04 - Processor IOs (R66.2), 11 - Expansion connectors (J16.31)
EXT40_GP5: 05 - Processor IO Expansions (U6.14), 11 - Expansion connectors (J16.16)
EXT40_GP6: 05 - Processor IO Expansions (U6.15), 11 - Expansion connectors (J16.18)
EXT40_GP7: 05 - Processor IO Expansions (U6.16), 11 - Expansion connectors (J16.37)
EXT40_GPIO_PA02: 04 - Processor IOs (R32.1), 11 - Expansion connectors (J16.11)
EXT40_GPIO_PA03: 04 - Processor IOs (R39.1), 11 - Expansion connectors (J16.15)
EXT40_GPIO_PA04: 04 - Processor IOs (R41.1), 11 - Expansion connectors (J16.13)
EXT40_GPIO_PA14: 04 - Processor IOs (R59.1), 11 - Expansion connectors (J16.22)
EXT40_GPIO_PB24: 04 - Processor IOs (R82.1), 11 - Expansion connectors (J16.36)
EXT40_I2SCK_PB19: 04 - Processor IOs (R69.1), 11 - Expansion connectors (J16.12)
EXT40_I2SDIN_PB21: 04 - Processor IOs (R74.1), 11 - Expansion connectors (J16.38)
EXT40_I2SDOUT_PB22: 04 - Processor IOs (R77.1), 11 - Expansion connectors (J16.40)
EXT40_I2SMCK_PB23: 04 - Processor IOs (R80.1), 11 - Expansion connectors (J16.7)
EXT40_I2SWS_PB20: 04 - Processor IOs (R71.1), 11 - Expansion connectors (J16.35)
EXT40_NPCS1_PA07: 04 - Processor IOs (R43.1), 11 - Expansion connectors (J16.24)
EXT40_NPCS2_PA08: 04 - Processor IOs (R45.1), 11 - Expansion connectors (J16.26)
EXT40_PWM0_PB11: 04 - Processor IOs (R60.2), 11 - Expansion connectors (J16.32)
EXT40_PWM1_PB12: 04 - Processor IOs (R63.2), 11 - Expansion connectors (J16.33)
EXT40_RXD: 05 - Processor IO Expansions (U16.5), 11 - Expansion connectors (J16.10)
EXT40_SPI_MISO_PA11: 04 - Processor IOs (R51.1), 11 - Expansion connectors (J16.21)
EXT40_SPI_MOSI_PA12: 04 - Processor IOs (R54.1), 11 - Expansion connectors (J16.19)
EXT40_SPI_SCLK_PA13: 04 - Processor IOs (R57.1), 11 - Expansion connectors (J16.23)
EXT40_TWCK: 05 - Processor IO Expansions (R78.2), 11 - Expansion connectors (J16.5)
EXT40_TWD: 05 - Processor IO Expansions (R68.2), 11 - Expansion connectors (J16.3)
EXT40_TXD: 05 - Processor IO Expansions (U16.6), 11 - Expansion connectors (J16.8)
FLEXCOM0_IO0_PA00: 04 - Processor IOs (U5.P2), 05 - Processor IO Expansions (R62.1 R64.1 R67.1 R68.1)
FLEXCOM0_IO1_PA01: 04 - Processor IOs (U5.M3), 05 - Processor IO Expansions (R61.1 R73.1 R76.1 R78.1)
FLEXCOM5_IO0_TX_PA22: 04 - Processor IOs (U5.G1), 05 - Processor IO Expansions (R156.2 R158.2)
FLEXCOM5_IO1_RX_PA21: 04 - Processor IOs (U5.G6), 05 - Processor IO Expansions (R157.2 R159.2)
FLEXCOM5_IO3_BT_CTS_PA08: 04 - Processor IOs (R44.1), 09 - Wi-Fi BT module (R171.2)
FLEXCOM5_IO4_BT_RTS_PA07: 04 - Processor IOs (R42.1), 09 - Wi-Fi BT module (R173.2)
FLEXCOM6_TWCK_PA31: 04 - Processor IOs (U5.H4), 05 - Processor IO Expansions (5 pins)
FLEXCOM6_TWD_PA30: 04 - Processor IOs (U5.G2), 05 - Processor IO Expansions (5 pins)
JTAG_CONN_nRST: 12 - User Interaction (R260.1 R265.1), 13 - On Board JLINK (U32.11)
JTAG_CONN_RTCK: 12 - User Interaction (J23.11 R259.2), 13 - On Board JLINK (U32.3)
JTAG_CONN_TCK: 12 - User Interaction (J23.9 R258.2), 13 - On Board JLINK (U31.2)
JTAG_CONN_TDI: 12 - User Interaction (J23.5 R256.1), 13 - On Board JLINK (U31.5)
JTAG_CONN_TDO: 12 - User Interaction (J23.13), 13 - On Board JLINK (U31.11)
JTAG_CONN_TMS: 12 - User Interaction (J23.7 R257.1), 13 - On Board JLINK (U31.14)
JTAG_nRST: 03 - Processor SAM9X60 (R191.1), 13 - On Board JLINK (U32.10 U32.13)
JTAG_RTCK: 03 - Processor SAM9X60 (U5.T2), 13 - On Board JLINK (U32.4 U32.7)
JTAG_TCK: 03 - Processor SAM9X60 (U5.R3), 13 - On Board JLINK (U31.4)
JTAG_TDI: 03 - Processor SAM9X60 (U5.F3), 13 - On Board JLINK (U31.7)
JTAG_TDO: 03 - Processor SAM9X60 (U5.H5), 13 - On Board JLINK (U31.9)
JTAG_TMS: 03 - Processor SAM9X60 (U5.F5), 13 - On Board JLINK (U31.12)
LCD_D0_ISI_D0_PC00: 04 - Processor IOs (U5.M4), 11 - Expansion connectors (J15.3 R220.2)
LCD_D1_ISI_D1_PC01: 04 - Processor IOs (U5.P4), 11 - Expansion connectors (J15.4 R221.1)
LCD_D2_ISI_D2_PC02: 04 - Processor IOs (U5.N5), 11 - Expansion connectors (J15.5 R222.2)
LCD_D3_ISI_D3_PC03: 04 - Processor IOs (U5.P5), 11 - Expansion connectors (J15.6 R223.1)
LCD_D4_ISI_D4_PC04: 04 - Processor IOs (U5.L5), 11 - Expansion connectors (J15.8 R224.2)
LCD_D5_ISI_D5_PC05: 04 - Processor IOs (U5.R4), 11 - Expansion connectors (J15.9 R225.1)
LCD_D6_ISI_D6_PC06: 04 - Processor IOs (U5.M6), 11 - Expansion connectors (J15.10 R226.2)
LCD_D7_ISI_D7_PC07: 04 - Processor IOs (U5.T3), 11 - Expansion connectors (J15.11 R227.1)
LCD_D8_ISI_D8_PC08: 04 - Processor IOs (U5.N8), 11 - Expansion connectors (J15.13 R228.2)
LCD_D9_ISI_D9_PC09: 04 - Processor IOs (U5.T4), 11 - Expansion connectors (J15.14 R229.1)
LCD_D10_ISI_D10_PC10: 04 - Processor IOs (U5.P6), 11 - Expansion connectors (J15.15 R230.2)
LCD_D11_ISI_D11_PC11: 04 - Processor IOs (U5.N6), 11 - Expansion connectors (J15.16 R231.1)
LCD_D12_ISI_PCK_PC12: 04 - Processor IOs (U5.R5), 11 - Expansion connectors (J15.18 R219.2)
LCD_D13_ISI_VSYNC_PC13: 04 - Processor IOs (U5.L7), 11 - Expansion connectors (J15.19 R216.2)
LCD_D14_ISI_HSYNC_PC14: 04 - Processor IOs (U5.T5), 11 - Expansion connectors (J15.20 R218.2)
LCD_D15_ISI_MCK_PC15: 04 - Processor IOs (U5.J7), 11 - Expansion connectors (J15.21 R215.2)
LCD_D16_ISI_nRST_PC16: 04 - Processor IOs (U5.R6), 11 - Expansion connectors (J15.23 R212.1)
LCD_D17_PC17: 04 - Processor IOs (U5.K8), 11 - Expansion connectors (J15.24)
LCD_D18_PC18: 04 - Processor IOs (U5.T6), 11 - Expansion connectors (J15.25)
LCD_D19_PC19: 04 - Processor IOs (U5.L8), 11 - Expansion connectors (J15.26)
LCD_D20_PC20: 04 - Processor IOs (U5.P8), 11 - Expansion connectors (J15.28)
LCD_D21_PC21: 04 - Processor IOs (U5.M8), 11 - Expansion connectors (J15.29)
LCD_D22_PC22: 04 - Processor IOs (U5.R7), 11 - Expansion connectors (J15.30)
LCD_D23_PC23: 04 - Processor IOs (U5.K9), 11 - Expansion connectors (J15.31)
LCD_DATA_ENABLE_PC29: 04 - Processor IOs (U5.L10), 11 - Expansion connectors (J15.36)
LCD_HSYNC/WE_PC28: 04 - Processor IOs (U5.N9), 11 - Expansion connectors (J15.35)
LCD_ID_PD14: 04 - Processor IOs (U5.L12), 11 - Expansion connectors (J15.1)
LCD_IRQ1_PC25: 04 - Processor IOs (U5.L9), 11 - Expansion connectors (J15.44)
LCD_IRQ2_PB17: 04 - Processor IOs (U5.B1), 11 - Expansion connectors (J15.45)
LCD_ISI_ENABLE_PC24: 04 - Processor IOs (U5.R8), 11 - Expansion connectors (J15.41 R213.2)
LCD_ISI_TWCK: 05 - Processor IO Expansions (R73.2), 11 - Expansion connectors (J15.43 J17.7)
LCD_ISI_TWD: 05 - Processor IO Expansions (R64.2), 11 - Expansion connectors (J15.42 J17.8)
LCD_PCLK_PC30: 04 - Processor IOs (U5.T7), 11 - Expansion connectors (J15.33)
LCD_PWM_PC26: 04 - Processor IOs (U5.T8), 11 - Expansion connectors (J15.46)
LCD_VSYNC/CS_PC27: 04 - Processor IOs (U5.M9), 11 - Expansion connectors (J15.34)
MBUS_AD4_PB15: 04 - Processor IOs (U5.B5), 11 - Expansion connectors (J14.1)
MBUS_INT_PB18: 04 - Processor IOs (U5.E4), 11 - Expansion connectors (J14.15)
MBUS_MISO_PA11: 04 - Processor IOs (R50.1), 11 - Expansion connectors (J14.5)
MBUS_MOSI_PA12: 04 - Processor IOs (R53.1), 11 - Expansion connectors (J14.6)
MBUS_NPCS0_PA14: 04 - Processor IOs (R58.1), 11 - Expansion connectors (J14.3)
MBUS_PWM_PB13: 04 - Processor IOs (R65.2), 11 - Expansion connectors (J14.16)
MBUS_RST_PB14: 04 - Processor IOs (U5.F2), 11 - Expansion connectors (J14.2)
MBUS_RX: 05 - Processor IO Expansions (U21.5), 11 - Expansion connectors (J14.14)
MBUS_SPCK_PA13: 04 - Processor IOs (R56.1), 11 - Expansion connectors (J14.4)
MBUS_TWCK: 05 - Processor IO Expansions (R95.2), 11 - Expansion connectors (J14.12)
MBUS_TWD: 05 - Processor IO Expansions (R90.2), 11 - Expansion connectors (J14.11)
MBUS_TX: 05 - Processor IO Expansions (U21.6), 11 - Expansion connectors (J14.13)
MCP23008_INT_PD17: 04 - Processor IOs (U5.N16), 05 - Processor IO Expansions (R33.1 U6.7)
MIC2800_nRST: 02 - Power supply (Q5.3 R17.1 U3.12), 03 - Processor SAM9X60 (R185.1)
NAND_ALE_PD02: 04 - Processor IOs (U5.P15), 06 - On Board Memories (U9.17)
NAND_CLE_PD03: 04 - Processor IOs (U5.N14), 06 - On Board Memories (U9.16)
NAND_IO0_PD06: 04 - Processor IOs (U5.K16), 06 - On Board Memories (U9.29)
NAND_IO1_PD07: 04 - Processor IOs (U5.J12), 06 - On Board Memories (U9.30)
NAND_IO2_PD08: 04 - Processor IOs (U5.K15), 06 - On Board Memories (U9.31)
NAND_IO3_PD09: 04 - Processor IOs (U5.J10), 06 - On Board Memories (U9.32)
NAND_IO4_PD10: 04 - Processor IOs (U5.L16), 06 - On Board Memories (U9.41)
NAND_IO5_PD11: 04 - Processor IOs (U5.K11), 06 - On Board Memories (U9.42)
NAND_IO6_PD12: 04 - Processor IOs (U5.L15), 06 - On Board Memories (U9.43)
NAND_IO7_PD13: 04 - Processor IOs (U5.J15), 06 - On Board Memories (U9.44)
NAND_nCS_PD04: 04 - Processor IOs (U5.R16), 12 - User Interaction (U25.2)
NAND_nCS_PD04_enabled: 06 - On Board Memories (R114.1 U9.9), 12 - User Interaction (U25.4)
NAND_nRE_PD00: 04 - Processor IOs (U5.R14), 06 - On Board Memories (U9.8)
NAND_nWE_PD01: 04 - Processor IOs (U5.T15), 06 - On Board Memories (U9.18)
NAND_RB_PD05: 04 - Processor IOs (U5.N11), 06 - On Board Memories (R115.1 U9.7)
NRST_PB25: 04 - Processor IOs (U5.E2), 05 - Processor IO Expansions (R34.1 U6.4), 08 - Ethernet MAC (R130.2), 09 - Wi-Fi BT module (U24.7), 11 - Expansion connectors (J15.47)
PAC1710_INT: 02 - Power supply (R4.1 U2.7), 05 - Processor IO Expansions (U6.9)
PAC1710_TWCK: 02 - Power supply (U2.9), 05 - Processor IO Expansions (R94.2)
PAC1710_TWD: 02 - Power supply (U2.8), 05 - Processor IO Expansions (R89.2)
PAC1934_INT: 02 - Power supply (R12.1 U4.1), 05 - Processor IO Expansions (U6.10)
PAC1934_TWCK: 02 - Power supply (U4.4), 05 - Processor IO Expansions (R93.2)
PAC1934_TWD: 02 - Power supply (U4.5), 05 - Processor IO Expansions (R87.2)
PB11: 04 - Processor IOs (R60.1 U5.D6), 12 - User Interaction (R206.1)
PB12: 04 - Processor IOs (R63.1 U5.C2), 12 - User Interaction (R200.1)
PB13: 04 - Processor IOs (R65.1 R66.1 U5.A4), 12 - User Interaction (R195.1)
QSPI_CS_PB20: 04 - Processor IOs (R72.1), 12 - User Interaction (U26.2)
QSPI_CS_PB20_enabled: 06 - On Board Memories (R106.1 U8.1), 12 - User Interaction (U26.4)
QSPI_IO0_PB21: 04 - Processor IOs (R75.1), 06 - On Board Memories (R103.1 U8.5)
QSPI_IO1_PB22: 04 - Processor IOs (R79.1), 06 - On Board Memories (R102.1 U8.2)
QSPI_IO2_PB23: 04 - Processor IOs (R81.1), 06 - On Board Memories (R101.1 U8.3)
QSPI_IO3_PB24: 04 - Processor IOs (R85.1), 06 - On Board Memories (R100.1 U8.7)
QSPI_SCK_PB19: 04 - Processor IOs (R70.1), 06 - On Board Memories (R99.1 U8.6)
SDMMC0_CD_PA23: 04 - Processor IOs (U5.J4), 10 - SDMMC, CAN & CLASSD (J4.10 R108.1)
SDMMC0_CLK_PA17: 04 - Processor IOs (U5.J3), 10 - SDMMC, CAN & CLASSD (J4.5)
SDMMC0_CMD_PA16: 04 - Processor IOs (U5.K2), 10 - SDMMC, CAN & CLASSD (J4.2 R109.1)
SDMMC0_DAT0_PA15: 04 - Processor IOs (U5.H6), 10 - SDMMC, CAN & CLASSD (J4.7 R111.1)
SDMMC0_DAT1_PA18: 04 - Processor IOs (U5.J1), 10 - SDMMC, CAN & CLASSD (J4.8 R110.1)
SDMMC0_DAT2_PA19: 04 - Processor IOs (U5.J5), 10 - SDMMC, CAN & CLASSD (J4.9 R113.1)
SDMMC0_DAT3_PA20: 04 - Processor IOs (U5.J2), 10 - SDMMC, CAN & CLASSD (J4.1 R112.1)
SDMMC1_WILC3000_CK_PA13: 04 - Processor IOs (R55.1), 09 - Wi-Fi BT module (U24.22)
SDMMC1_WILC3000_CMD_PA12: 04 - Processor IOs (R52.1), 09 - Wi-Fi BT module (R167.1 U24.23)
SDMMC1_WILC3000_DAT0_PA11: 04 - Processor IOs (R46.1), 09 - Wi-Fi BT module (R166.1 U24.24)
SDMMC1_WILC3000_DAT1_PA02: 04 - Processor IOs (R31.1), 09 - Wi-Fi BT module (R165.1 U24.25)
SDMMC1_WILC3000_DAT2_PA03: 04 - Processor IOs (R38.1), 09 - Wi-Fi BT module (R164.1 U24.26)
SDMMC1_WILC3000_DAT3_PA04: 04 - Processor IOs (R40.1), 09 - Wi-Fi BT module (R163.1 U24.27)
SEL_FNCT1_PD19: 04 - Processor IOs (U5.P16), 05 - Processor IO Expansions (U14.1 U14.7 U16.1 U16.7)
SEL_FNCT2_PD20: 04 - Processor IOs (U5.M11), 05 - Processor IO Expansions (U15.1 U15.7 U17.1 U17.7)
SHDN: 02 - Power supply (R19.2), 03 - Processor SAM9X60 (U5.R11)
USBA_N: 03 - Processor SAM9X60 (U5.R12), 07 - USB ports (J7.2)
USBA_P: 03 - Processor SAM9X60 (U5.T12), 07 - USB ports (J7.3)
USBA_VBUSDETECT_PB16: 04 - Processor IOs (U5.B3), 07 - USB ports (R148.2 R150.2)
USBB_EN_5V_PD15: 04 - Processor IOs (U5.M16), 07 - USB ports (R153.2 U19.1)
USBB_N: 03 - Processor SAM9X60 (U5.T14), 07 - USB ports (J8.2)
USBB_OVCUR: 05 - Processor IO Expansions (U6.12), 07 - USB ports (R152.1 U19.2)
USBB_P: 03 - Processor SAM9X60 (U5.T13), 07 - USB ports (J8.3)
USBC_EN_5V_PD16: 04 - Processor IOs (U5.M14), 07 - USB ports (R155.2 U20.1)
USBC_N: 03 - Processor SAM9X60 (U5.N12), 07 - USB ports (J8.6)
USBC_OVCUR: 05 - Processor IO Expansions (U6.13), 07 - USB ports (R154.1 U20.2)
USBC_P: 03 - Processor SAM9X60 (U5.P12), 07 - USB ports (J8.7)
USER_BUTTON_PD18: 04 - Processor IOs (U5.L13), 12 - User Interaction (R192.1)
USER_nRST: 03 - Processor SAM9X60 (R190.1), 12 - User Interaction (C145.1 SW3.1 SW3.2)
WAKE_UP: 03 - Processor SAM9X60 (U5.T11), 12 - User Interaction (R197.1)
WILC3000_ENABLE_PA29: 04 - Processor IOs (U5.H3), 05 - Processor IO Expansions (U21.1 U21.7 U23.1 U23.7), 09 - Wi-Fi BT module (U22.3)
WILC3000_INTERRUPT_PA28: 04 - Processor IOs (U5.F1), 09 - Wi-Fi BT module (R168.1 U24.33)
WILC_BT_RX: 05 - Processor IO Expansions (U23.6), 09 - Wi-Fi BT module (R170.2)
WILC_BT_TX: 05 - Processor IO Expansions (U23.5), 09 - Wi-Fi BT module (R169.2)

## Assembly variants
Standard: not fitted C24 C25 C91 C92 C132 C135 C151 C152 J9 J10 J19 JP5 LCD1 R21 R22 R24 R27 R35 R36 R37 R91 R99 R100 R101 R102 R103 R104 R105 R117 R118 R126 R128 R133 R163 R164 R165 R166 R167 R172 R207 R208 R209 R210 R211 R217 R239 R258 R259 R261 R262 Y1 Y5 Y7 Y9
Standard_WILC3000_DNP: not fitted C24 C25 C91 C92 C132 C135 C151 C152 J9 J10 J19 JP5 LCD1 R21 R22 R24 R27 R35 R36 R37 R91 R99 R100 R101 R102 R103 R104 R105 R117 R118 R126 R128 R133 R163 R164 R165 R166 R167 R172 R207 R208 R209 R210 R211 R217 R239 R258 R259 R261 R262 U24 Y1 Y5 Y7 Y9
